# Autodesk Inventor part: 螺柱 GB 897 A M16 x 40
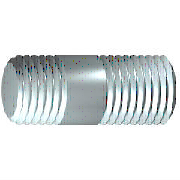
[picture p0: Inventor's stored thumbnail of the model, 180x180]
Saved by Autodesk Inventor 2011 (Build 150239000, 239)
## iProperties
Created: 2010-02
Part Number: 螺柱 GB 897 A M16 x 40
Material: 低炭钢
Description: 双头螺柱 - bm = 1 d
Document SubType Name: Modeling
Standard: GB/T 897-1988
Designer: Administrator
Standard Revision: 1988
Standards Organization: GB
Language: zh-CN
Size Designation: A M16x40
Categories: <MemberInstance><Categories><Category DisplayName="紧固件" InternalName="e4da775c-781d-43d5-af7c-5136215cf5a6" Mnemonic="FSTN"><Category DisplayName="螺栓" InternalN
Density: 1 g/cm^3
IsCustomPart: 1
Author: Administrator
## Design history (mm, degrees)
sketch "Sketch1"
  geometry: L1 (45, 8)-(45, 0); L2 (-11, 0)-(45, 0); L3 (-22.2, 0)-(56.2, 0) reference; L4 (0, 9.6)-(0, -1.6) reference; L5 (-11, 8)-(-11, 0); L6 (15, 8)-(15, 0); L7 (-22.2, 0)-(56.2, 0) reference; L8 (-11, 8)-(0, 8); L9 (0, 8)-(1.8, 7.351); L10 (1.8, 7.351)-(5, 8); L11 (5, 8)-(10, 8); L12 (10, 8)-(13.2, 7.351); L13 (13.2, 7.351)-(15, 8); L14 (15, 8)-(45, 8)
  constraints: 22 end point, 5 point on line, 3 perpendicular, 2 collinear, 1 parallel
  dimensions: "d6" = 30 distance from line of L1 L6.start (= GEL); "d13" = 16 diameter of L8 L2 (= GD); "d87" = 14.701 diameter of L9.end L2 (= MD); "d88" = 5 distance of L10.end L8.end (= GAL); "d90" = 14.701 diameter of L12.end L2 (= MD); "d91" = 5 distance of L6.start L11.end (= GAL); "d93" = 1.8 horizontal distance of L8.end L9.end (= 0.9 x PTC); "d94" = 1.8 horizontal distance of L6.start L12.end (= 0.9 x PTC); "d95" = 40 distance from line of L10.end L1 (= NLG); "d4" = 16 distance from line of L10.end L5 (= KOH)
revolve "Body" sketch "Sketch1" stored, may be unused: angle "d3" = 90 deg
thread "Thread1" dims "d1" = 11 (= GEL1), "d2" = 0
thread "Thread2" dims "d7" = 30 (= GEL), "d8" = 0
chamfer "Chamfer1" distance "d9" = 1.2279 (computed from GUL); stored, may be unused: second distance "d10" = 1.42837 (= -0.5 x SPD + 0.5 x GD), angle "d69" = 45 deg
chamfer "Chamfer2" distance "d11" = 1.2279 (computed from GUL1); stored, may be unused: second distance "d12" = 1.42837 (= -0.5 x SPD + 0.5 x GD), angle "d70" = 45 deg
body "Solid1"
workplane "Work Plane1"
other parameters: "NLG" = 40 [user parameter; used in 1 equation term], "GEL" = 30 [user parameter; used in 3 equation terms], "GAL" = 5 [user parameter; used in 4 equation terms], "SPD" = 13.14325 [user parameter; used in 2 equation terms], "d0" = 16 (= GD), "GUL" = 1.2269 (= 0.61345 x PTC) [user parameter; used in 3 equation terms], "KOH" = 16 [user parameter; used in 3 equation terms], "GD" = 16 (= NND) [user parameter; used in 4 equation terms], "BDM" = 16 [user parameter], "GUL1" = 1.2269 (= GUL) [user parameter; used in 2 equation terms], "GAL1" = 5 (= GAL) [user parameter], "d78" = 0, "d80" = -31.2269 (= -GUL - GEL), "d86" = -14.7731 (= -KOH + GUL1), "MD" = 14.701 [user parameter; used in 2 equation terms], "PTC" = 2 [user parameter; used in 5 equation terms], "GEL1" = 11 (= KOH - GAL) [user parameter; used in 1 equation term], "TPU" = 5 (computed from PTC) [user parameter], "THREADDIA" = 16 [user parameter; used in 1 equation term], "TOA" = 30 deg [user parameter], "FAWI" = 45 deg [user parameter; used in 1 equation term], "NND" = 16 [user parameter; used in 1 equation term], "FAWI1" = 45 deg (= FAWI) [user parameter], "GD1" = 13.5462 (= THREADDIA - 1.2269 x PTC) [user parameter]
